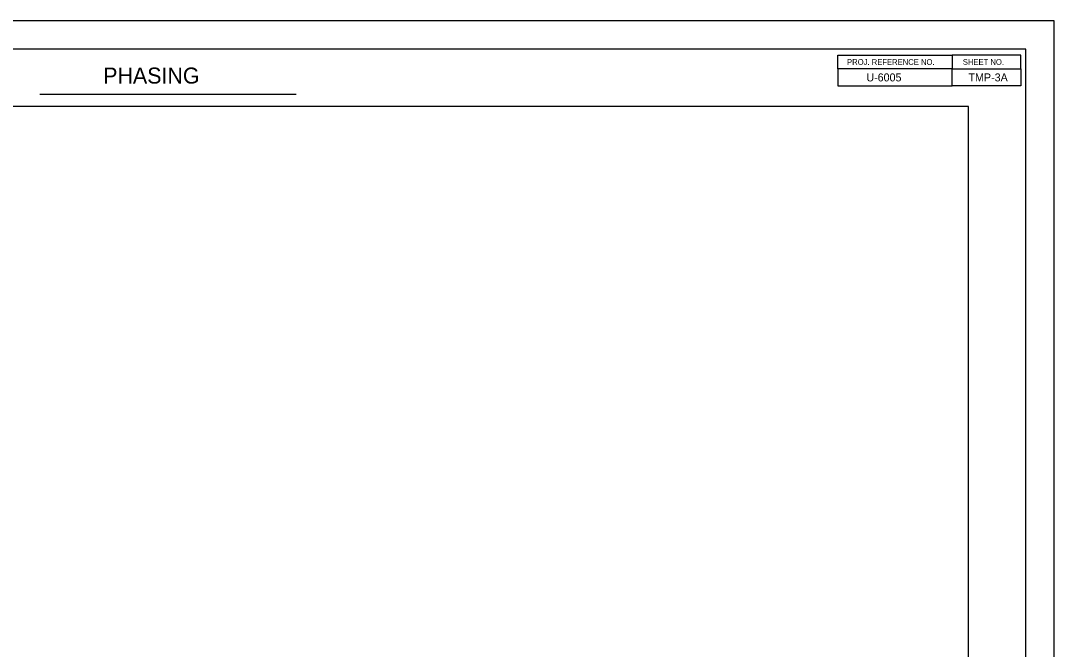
# Model space of a CAD drawing. Extents: x 764226 to 769781, y 650021 to 652521.
# Drawn here: x 767233 to 768137, y 650571 to 651121 of the extents above; entities that cross this region are included whole.
import ezdxf

# ---------------------------------------------------------------- set-up
doc = ezdxf.new("R2010")
doc.units = 0
for name, color, linetype in [('DEV BORDER CELL', 7, 'Continuous'), ('DEV TRANSPORTATION OPERATIONS PLAN SHEET', 7, 'Continuous'), ('Scratch_Level_0', 7, 'Continuous'), ('Sheet Plot Border Outside CELL', 7, 'Continuous')]:
    doc.layers.add(name, color=color, linetype=linetype)

msp = doc.modelspace()

# ---------------------------------------------------------------- linework, layer by layer
at = {"layer": 'DEV BORDER CELL'}
for p, q in [((768047.99, 651078.94), (768107.99, 651078.94)), ((767250.33, 651056.91), (767474.35, 651056.91))]:
    msp.add_line(p, q, dxfattribs=at)
for points in [[(768112.34, 651096.08), (766612.34, 651096.09), (766612.34, 650046.08), (768112.34, 650046.08)], [(767947.99, 651090.94), (768047.99, 651090.94), (768047.99, 651078.94), (767947.99, 651078.94)], [(768047.99, 651078.94), (768107.99, 651078.94), (768107.99, 651090.94), (768047.99, 651090.94)], [(768047.99, 651078.94), (767947.99, 651078.94), (767947.99, 651063.94), (768047.99, 651063.94)], [(768047.99, 651078.94), (768107.99, 651078.94), (768107.99, 651063.94), (768047.99, 651063.94)]]:
    msp.add_lwpolyline(points, close=True, dxfattribs=at)
at = {"layer": 'Scratch_Level_0'}
msp.add_lwpolyline([(768062.34, 651046.08), (766662.34, 651046.09), (766662.34, 650096.08), (767541.19, 650096.08), (767541.19, 650214.35), (768062.34, 650214.35)], close=True, dxfattribs=at)
at = {"layer": 'Sheet Plot Border Outside CELL'}
msp.add_lwpolyline([(766449.34, 650021.08), (768137.34, 650021.08), (768137.34, 651121.08), (766449.34, 651121.08)], close=True, dxfattribs=at)

# ---------------------------------------------------------------- texts
at = {"layer": 'DEV BORDER CELL'}
for s, height, p in [('PROJ. REFERENCE NO.', 4.9992, (767956.1, 651082.44)), ('SHEET NO.', 4.999, (768057.32, 651082.44))]:
    msp.add_text(s, height=height, rotation=0.00056, dxfattribs=at).set_placement(p)
for s, p in [('U-6005', (767972.98, 651067.94)), ('TMP-3A', (768062.28, 651067.94))]:
    msp.add_text(s, height=7, dxfattribs=at).set_placement(p)
at = {"layer": 'DEV TRANSPORTATION OPERATIONS PLAN SHEET'}
msp.add_text('PHASING', height=14, dxfattribs=at).set_placement((767305.6, 651066.06))

doc.saveas('drawing.dxf')
